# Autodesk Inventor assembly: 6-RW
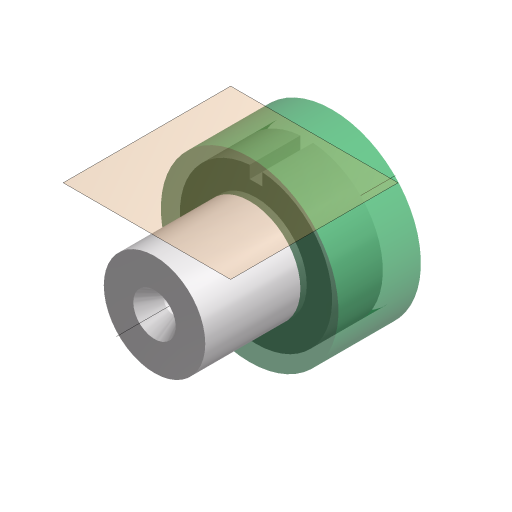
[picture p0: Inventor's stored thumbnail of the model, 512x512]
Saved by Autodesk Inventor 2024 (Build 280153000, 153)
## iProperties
Created: 2023-03
Part Number: 6-RW
Document SubType Name: Assembly
Designer: Andrzej Jaskulski
Manufacturer: Standard
Standards Organization: Custom
Checked By: A.J.
Engr Approved By: Andrzej Jaskulski
Mfg Approved By: Andrzej Jaskulski
Authority: A.J.
Company: ATC
Title: A.J.: Kurs R2024-MEP
Author: Andrzej Jaskulski
Revision Number: 1/24
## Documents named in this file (3)
- C:\Users\AndJas\Documents\R2024-MEP\Obszar roboczy\FUSION\F1-Modelowanie Zespołu.iam
- C:\Users\AndJas\Documents\R2024-MEP\Obszar roboczy\FUSION\F-WAŁEK.ipt
- C:\Users\AndJas\Documents\R2024-MEP\Obszar roboczy\FUSION\F-TULEJA.ipt
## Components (2 placed, 2 different names)
1. F-WAŁEK:1 — Wstaw:1
2. F-TULEJA:1 — Wstaw:1
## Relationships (1: Insert 1)
- Wstaw:1 [Insert]: F-WAŁEK:1 ↔ F-TULEJA:1
